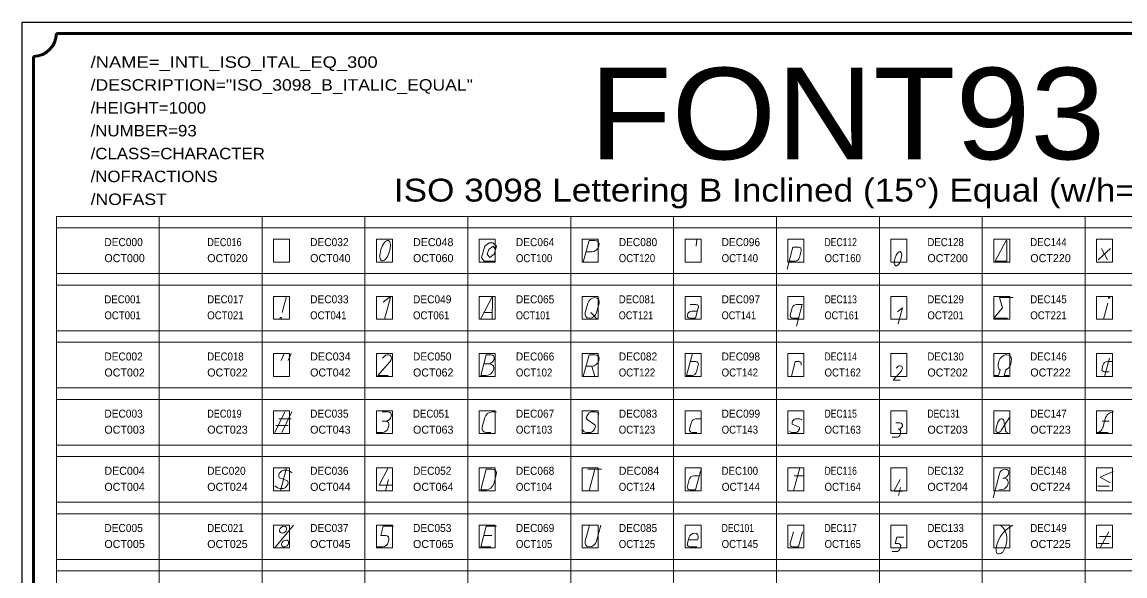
# Model space of a CAD drawing. Extents: x -200 to 7300, y -200 to 4800.
# Drawn here: x -200 to 4624, y 2378 to 4800 of the extents above; entities that cross this region are included whole.
import ezdxf
from ezdxf.enums import TextEntityAlignment as Align

# ---------------------------------------------------------------- set-up
doc = ezdxf.new("R2010")
doc.units = 0
doc.header["$LTSCALE"] = 14
for name, color, linetype, lineweight in [('1', 7, 'Continuous', 13), ('5', 7, 'Continuous', 40), ('6', 7, 'Continuous', 13), ('63', 7, 'Continuous', 13)]:
    doc.layers.add(name, color=color, linetype=linetype, lineweight=lineweight)
doc.layers.add('10', color=7, linetype='Continuous')
doc.layers.add('11', color=7, linetype='Continuous')

msp = doc.modelspace()

# ---------------------------------------------------------------- linework, layer by layer
at = {"layer": '1'}
for p, q in [((2749, 3820), (2752, 3850)), ((2292, 3795), (2267, 3795)), ((3208, 3800), (3200, 3770)), ((4507, 3760), (4561, 3810)), ((4521, 3810), (4547, 3760)), ((3181, 3755), (3156, 3755)), ((938, 3530), (957, 3600)), ((2274, 3570), (2263, 3530)), ((2324, 3570), (2313, 3530)), ((4549, 3570), (4530, 3500)), ((1821, 3530), (1857, 3530)), ((2315, 3500), (2288, 3530)), ((2722, 3565), (2747, 3565)), ((2729, 3535), (2754, 3535)), ((3168, 3550), (3160, 3520)), ((3171, 3505), (3196, 3505)), ((934, 3320), (947, 3350)), ((977, 3350), (964, 3320)), ((4556, 3330), (4535, 3250)), ((1845, 3305), (1820, 3305)), ((2292, 3295), (2267, 3295)), ((2305, 3250), (2292, 3295)), ((2747, 3315), (2722, 3315)), ((2750, 3270), (2758, 3300)), ((4072, 3315), (4070, 3305)), ((4127, 3315), (4125, 3305)), ((4528, 3300), (4524, 3285)), ((4567, 3315), (4547, 3315)), ((4535, 3270), (4555, 3270)), ((906, 3005), (950, 3095)), ((936, 3005), (980, 3095)), ((1400, 3095), (1375, 3095)), ((1875, 3095), (1855, 3095)), ((923, 3065), (977, 3065)), ((1390, 3055), (1375, 3055)), ((1824, 3070), (1813, 3030)), ((2728, 3050), (2720, 3020)), ((2767, 3065), (2747, 3065)), ((3168.8, 3041), (3199.6, 3029)), ((3640, 3047), (3622, 3047)), ((4068, 3050), (4060, 3020)), ((4119, 3070), (4083, 3015)), ((4101, 3016), (4093.7, 3055.8)), ((4525, 3055), (4555, 3055)), ((4527, 3025), (4537, 3065)), ((910, 3035), (964, 3035)), ((1376, 3005), (1351, 3005)), ((1404, 3035), (1402, 3025)), ((1831, 3005), (1851, 3005)), ((2731, 3005), (2751, 3005)), ((3633, 3019), (3632.8, 3019)), ((3643, 3005), (3641.3, 2998)), ((4551, 3005), (4501, 3005)), ((3624, 2984), (3606, 2984)), ((957, 2850), (930, 2750)), ((3202, 2850), (3175, 2750)), ((1390, 2750), (1403, 2800)), ((1874, 2820), (1863, 2780)), ((2275, 2845), (2335, 2845)), ((2305, 2845), (2280, 2750)), ((2710, 2770), (2718, 2800)), ((2737, 2815), (2762, 2815)), ((3177, 2815), (3217, 2815)), ((4047, 2720), (4075, 2825)), ((4089.6, 2805), (4094.6, 2805)), ((3633, 2730), (3642, 2765)), ((4505, 2770), (4555, 2770)), ((905, 2500), (987, 2600)), ((2282, 2600), (2263, 2530)), ((2332, 2600), (2313, 2530)), ((3174, 2570), (3160, 2520)), ((4515, 2500), (4554, 2570)), ((1404, 2535), (1402, 2525)), ((1855, 2555), (1820, 2555)), ((2710, 2520), (2717, 2545)), ((4505, 2520), (4555, 2520)), ((4513, 2550), (4563, 2550)), ((1351, 2505), (1376.6, 2505)), ((2751, 2505), (2721, 2505)), ((3606, 2484), (3624, 2484)), ((3643, 2505), (3641, 2498))]:
    msp.add_line(p, q, dxfattribs=at)
for points in [[(1871, 3755), (1821, 3755), (1810, 3770), (1824, 3820), (1843, 3835), (1859, 3835), (1875, 3820), (1865, 3785), (1846, 3770), (1835, 3785), (1841, 3805), (1860, 3820), (1871, 3805)], [(2305, 3845), (2280, 3845), (2255, 3750)], [(3147, 3720), (3172, 3815), (3197, 3815)], [(1385, 3500), (1411, 3595), (1406, 3595), (1380, 3575)], [(1805, 3500), (1855, 3595), (1858, 3595), (1856, 3500)], [(4135, 3595), (4075, 3595), (4088, 3550), (4051, 3505), (4111, 3505)], [(2758, 3550), (2746, 3505), (2721, 3505)], [(3187, 3470), (3212, 3565), (3187, 3565)], [(3632, 3480), (3651, 3550), (3629, 3533)], [(1850, 3345), (1830, 3345), (1806, 3255), (1831, 3255)], [(2305, 3345), (2280, 3345), (2255, 3250)], [(2732, 3350), (2706, 3255), (2731, 3255)], [(1401, 3255), (1356, 3255), (1409, 3314)], [(3197, 3315), (3182, 3315), (3165, 3250)], [(3641, 3234), (3610, 3234), (3646, 3275)], [(4051, 3255), (4071, 3255), (4078, 3279)], [(4116, 3255), (4096, 3255), (4103, 3279)], [(2322, 3083), (2322, 3088), (2318, 3092), (2314, 3094), (2307, 3095), (2290, 3095), (2286, 3094), (2281, 3091), (2276, 3085), (2273, 3081), (2271, 3077), (2268, 3069), (2272, 3062), (2305, 3038), (2308, 3031), (2306, 3023), (2304, 3019), (2301, 3015), (2295, 3009), (2291, 3006), (2286, 3005), (2269, 3005), (2263, 3006), (2259, 3008), (2255, 3012), (2255, 3017)], [(1417, 2775), (1362, 2775), (1402, 2850)], [(2772, 2850), (2746, 2755), (2721, 2755)], [(981, 2828), (968, 2837), (959, 2840), (944, 2840), (940, 2839), (935, 2836), (928.6, 2830.8), (925, 2827), (923, 2819), (923.2, 2813), (925.5, 2807.1), (961, 2793), (964, 2786), (962, 2778), (960, 2774), (957, 2770), (952, 2764), (947, 2761), (943, 2760), (928, 2760), (918, 2763), (906, 2772)], [(1855, 2845), (1830, 2845), (1806, 2755), (1831, 2755)], [(3651, 2748), (3613, 2748), (3641, 2800)], [(4573, 2835), (4516, 2810), (4559, 2785)], [(1425, 2595), (1380, 2595), (1370, 2555), (1390, 2555)], [(1875, 2595), (1830, 2595), (1806, 2505), (1851, 2505)], [(3171, 2505), (3196, 2505), (3214, 2570)], [(2714, 2535), (2754, 2535), (2757, 2545)], [(3657, 2547), (3626, 2547), (3619, 2519), (3633, 2519)]]:
    msp.add_lwpolyline(points, dxfattribs=at)
for points in [[(4056, 3755), (4107, 3755), (4108, 3845), (4105, 3845)], [(4551, 3592), (4557, 3592), (4559, 3598), (4553, 3598)], [(927, 3502), (933, 3502), (935, 3508), (929, 3508)]]:
    msp.add_lwpolyline(points, close=True, dxfattribs=at)
for centre, major_axis, ratio in [((1388.16, 3800), (14.6, 44.6), 0.408607), ((3631.31, 3765), (10.22, 31.22), 0.408607), ((941.76, 2579.84), (-12.94, -11.3), 0.762607), ((950.45, 2519.85), (-12.94, -11.3), 0.762607)]:
    msp.add_ellipse(centre, major_axis=major_axis, ratio=ratio, dxfattribs=at)
for centre, major_axis, ratio, start_param, end_param in [((2298.3, 3820), (21.5, 18.81), 0.765566, 3.860429, 7.0020216), ((3193, 3800), (-12.9, -11.29), 0.765566, 2.2896327, 3.860429), ((3185.15, 3770), (-12.9, -11.29), 0.765566, 0.7188363, 2.2896326), ((2299, 3570), (-21.5, -18.81), 0.765566, 2.2896326, 5.4312252), ((2288, 3530), (21.5, 18.81), 0.765566, 2.2896328, 5.4312254), ((2725.02, 3520), (-12.9, -11.29), 0.765566, 3.860429, 7.0020216), ((2743.2, 3550), (-12.9, -11.29), 0.765566, 2.2896327, 3.860429), ((3182.98, 3550), (-12.9, -11.29), 0.765566, 3.860429, 5.4312252), ((3175.02, 3520), (12.9, 11.29), 0.765566, 2.2896328, 3.860429), ((1395.12, 3324.87), (-17.2, -15.05), 0.765566, 1.7153279, 5.1862467), ((1844.9, 3325), (17.2, 15.05), 0.765566, 3.860429, 7.0020216), ((2298.3, 3320), (21.5, 18.81), 0.765566, 3.860429, 7.0020216), ((4099.5, 3315), (-21.63, -25.32), 0.743855, 2.1369211, 5.2785137), ((1837.84, 3280), (21.5, 18.81), 0.765566, 3.860429, 7.0020216), ((2743, 3300), (-12.9, -11.29), 0.765566, 2.2896327, 3.860429), ((3192.98, 3300), (-12.9, -11.29), 0.765566, 2.2896327, 3.860429), ((3636.28, 3282.61), (-12.04, -10.54), 0.765566, 1.7153279, 5.1862467), ((4100, 3305), (-25.87, -22.6), 0.762607, 5.4301257, 6.4773233), ((4095, 3305), (-25.87, -22.6), 0.762607, 1.2413355, 2.2885329), ((4539.02, 3285), (12.9, 11.29), 0.765566, 2.2896328, 3.860429), ((4543, 3300), (-12.9, -11.29), 0.765566, 3.860429, 5.4312252), ((2735, 3270), (-12.9, -11.29), 0.765566, 0.7188363, 2.2896326), ((1394.91, 3075), (17.2, 15.05), 0.765566, 3.860429, 7.0020216), ((1849, 3070), (-21.5, -18.81), 0.765566, 3.860429, 5.4312252), ((4567.27, 3065), (25.8, 22.58), 0.765566, 0.7188365, 2.2896328), ((1384.19, 3035), (-17.2, -15.05), 0.765566, 2.2896326, 3.8604289), ((2742.98, 3050), (-12.9, -11.29), 0.765566, 3.860429, 5.4312252), ((3183.23, 3050), (-12.9, -11.29), 0.765566, 4.1387286, 6.0747263), ((3190.91, 3060), (-20.04, -0.36), 0.248806, 3.0702852, 5.1041698), ((3636.26, 3032.98), (-12.06, -10.55), 0.765566, 0.7710374, 3.8615683), ((4080.72, 3049.84), (-8.85, -13.65), 0.702522, 2.4028539, 5.1395547), ((1381.51, 3025), (17.2, 15.05), 0.765566, 3.860429, 5.4312252), ((1838, 3030), (21.5, 18.81), 0.765566, 2.2896328, 3.860429), ((2735.02, 3020), (12.9, 11.29), 0.765566, 2.2896328, 3.860429), ((3177.37, 3010.06), (-20.04, -0.36), 0.248806, 6.2118779, 8.2948037), ((3185.2, 3020), (-12.9, -11.29), 0.765566, 1.0312547, 2.9331337), ((3627.31, 2998), (12.04, 10.54), 0.765566, 3.860429, 5.4312252), ((3629, 3005), (-12.04, -10.54), 0.765566, 2.2896326, 3.8604293), ((4072.64, 3019.84), (-8.94, -13.61), 0.705186, 5.1460808, 8.0584106), ((4116.54, 3020.31), (12.94, 11.3), 0.762607, 2.5799897, 3.8593292), ((4506.55, 3025), (-17.2, -15.05), 0.765566, 0.7188363, 2.2896326), ((1849, 2820), (-21.5, -18.81), 0.765566, 2.2896326, 3.8604289), ((2732.98, 2800), (-12.9, -11.29), 0.765566, 3.860429, 5.4312252), ((4094.96, 2825), (-17.2, -15.05), 0.765566, 0.7188364, 5.4312253), ((4087.9, 2780), (-21.5, -18.81), 0.765566, 0.4738577, 3.8604291), ((1838, 2780), (-21.5, -18.81), 0.765566, 0.7188363, 2.2896326), ((2725.02, 2770), (12.9, 11.29), 0.765566, 2.2896328, 3.860429), ((2736.92, 2545), (-17.2, -15.05), 0.765566, 2.2896326, 5.4312252), ((4163.9, 2515), (-86.02, -75.26), 0.765566, 4.4152401, 5.7335524), ((4003.9, 2515), (-86.02, -75.26), 0.765566, 1.9520105, 3.3056179), ((1382, 2525), (-17.2, -15.05), 0.765566, 0.7188366, 2.2896326), ((1384.22, 2535), (-17.2, -15.05), 0.765566, 2.2896326, 3.8604289), ((2288, 2530), (21.5, 18.81), 0.765566, 2.2896328, 5.4312254), ((2725.02, 2520), (12.9, 11.29), 0.765566, 2.2896328, 3.860429), ((3175.02, 2520), (12.9, 11.29), 0.765566, 2.2896328, 3.860429), ((3629, 2505), (-12.04, -10.54), 0.765566, 2.2896326, 3.8604289), ((3627, 2498), (12.04, 10.54), 0.765566, 3.860429, 5.4312252), ((4077.2, 2490), (-13.76, -12.04), 0.772879, 5.7364599, 8.0536718)]:
    msp.add_ellipse(centre, major_axis=major_axis, ratio=ratio, start_param=start_param, end_param=end_param, dxfattribs=at)
at = {"layer": '5', "lineweight": 53}
for p, q in [((-50, 4750), (7150, 4750)), ((-150, -50), (-150, 4650))]:
    msp.add_line(p, q, dxfattribs=at)
at = {"layer": '5', "lineweight": 25}
msp.add_lwpolyline([(-200, -200), (-200, 4800), (7300, 4800), (7300, -200)], close=True, dxfattribs=at)
at = {"layer": '5', "lineweight": 53}
msp.add_arc((-150, 4750), 100, 270, 0, dxfattribs=at)
at = {"layer": '6'}
for p, q in [((-50, 3950), (7150, 3950)), ((-50, 3950), (-50, -50)), ((400, 3950), (400, -50)), ((850, 3950), (850, -50)), ((1300, 3950), (1300, -50)), ((1750, 3950), (1750, -50)), ((2200, 3950), (2200, -50)), ((2650, 3950), (2650, -50)), ((3100, 3950), (3100, -50)), ((3550, 3950), (3550, -50)), ((4000, 3950), (4000, -50)), ((4450, 3950), (4450, -50)), ((-50, 3900), (7150, 3900)), ((-50, 3700), (7150, 3700)), ((-50, 3650), (7150, 3650)), ((-50, 3450), (7150, 3450)), ((-50, 3400), (7150, 3400)), ((-50, 3200), (7150, 3200)), ((-50, 3150), (7150, 3150)), ((-50, 2950), (7150, 2950)), ((-50, 2900), (7150, 2900)), ((-50, 2700), (7150, 2700)), ((-50, 2650), (7150, 2650)), ((-50, 2450), (7150, 2450)), ((-50, 2400), (7150, 2400))]:
    msp.add_line(p, q, dxfattribs=at)
at = {"layer": '63'}
for points in [[(900, 3750), (970, 3750), (970, 3850), (900, 3850)], [(1350, 3750), (1420, 3750), (1420, 3850), (1350, 3850)], [(1800, 3750), (1870, 3750), (1870, 3850), (1800, 3850)], [(2250, 3750), (2320, 3750), (2320, 3850), (2250, 3850)], [(2700, 3750), (2770, 3750), (2770, 3850), (2700, 3850)], [(3150, 3750), (3220, 3750), (3220, 3850), (3150, 3850)], [(3600, 3750), (3670, 3750), (3670, 3850), (3600, 3850)], [(4050, 3750), (4120, 3750), (4120, 3850), (4050, 3850)], [(4500, 3750), (4570, 3750), (4570, 3850), (4500, 3850)], [(900, 3500), (970, 3500), (970, 3600), (900, 3600)], [(1350, 3500), (1420, 3500), (1420, 3600), (1350, 3600)], [(1800, 3500), (1870, 3500), (1870, 3600), (1800, 3600)], [(2250, 3500), (2320, 3500), (2320, 3600), (2250, 3600)], [(2700, 3500), (2770, 3500), (2770, 3600), (2700, 3600)], [(3150, 3500), (3220, 3500), (3220, 3600), (3150, 3600)], [(3600, 3500), (3670, 3500), (3670, 3600), (3600, 3600)], [(4050, 3500), (4120, 3500), (4120, 3600), (4050, 3600)], [(4500, 3500), (4570, 3500), (4570, 3600), (4500, 3600)], [(900, 3250), (970, 3250), (970, 3350), (900, 3350)], [(1350, 3250), (1420, 3250), (1420, 3350), (1350, 3350)], [(1800, 3250), (1870, 3250), (1870, 3350), (1800, 3350)], [(2250, 3250), (2320, 3250), (2320, 3350), (2250, 3350)], [(2700, 3250), (2770, 3250), (2770, 3350), (2700, 3350)], [(3150, 3250), (3220, 3250), (3220, 3350), (3150, 3350)], [(3600, 3250), (3670, 3250), (3670, 3350), (3600, 3350)], [(4050, 3250), (4120, 3250), (4120, 3350), (4050, 3350)], [(4500, 3250), (4570, 3250), (4570, 3350), (4500, 3350)], [(900, 3000), (970, 3000), (970, 3100), (900, 3100)], [(1350, 3000), (1420, 3000), (1420, 3100), (1350, 3100)], [(1800, 3000), (1870, 3000), (1870, 3100), (1800, 3100)], [(2250, 3000), (2320, 3000), (2320, 3100), (2250, 3100)], [(2700, 3000), (2770, 3000), (2770, 3100), (2700, 3100)], [(3150, 3000), (3220, 3000), (3220, 3100), (3150, 3100)], [(3600, 3000), (3670, 3000), (3670, 3100), (3600, 3100)], [(4050, 3000), (4120, 3000), (4120, 3100), (4050, 3100)], [(4500, 3000), (4570, 3000), (4570, 3100), (4500, 3100)], [(900, 2750), (970, 2750), (970, 2850), (900, 2850)], [(1350, 2750), (1420, 2750), (1420, 2850), (1350, 2850)], [(1800, 2750), (1870, 2750), (1870, 2850), (1800, 2850)], [(2250, 2750), (2320, 2750), (2320, 2850), (2250, 2850)], [(2700, 2750), (2770, 2750), (2770, 2850), (2700, 2850)], [(3150, 2750), (3220, 2750), (3220, 2850), (3150, 2850)], [(3600, 2750), (3670, 2750), (3670, 2850), (3600, 2850)], [(4050, 2750), (4120, 2750), (4120, 2850), (4050, 2850)], [(4500, 2750), (4570, 2750), (4570, 2850), (4500, 2850)], [(900, 2500), (970, 2500), (970, 2600), (900, 2600)], [(1350, 2500), (1420, 2500), (1420, 2600), (1350, 2600)], [(1800, 2500), (1870, 2500), (1870, 2600), (1800, 2600)], [(2250, 2500), (2320, 2500), (2320, 2600), (2250, 2600)], [(2700, 2500), (2770, 2500), (2770, 2600), (2700, 2600)], [(3150, 2500), (3220, 2500), (3220, 2600), (3150, 2600)], [(3600, 2500), (3670, 2500), (3670, 2600), (3600, 2600)], [(4050, 2500), (4120, 2500), (4120, 2600), (4050, 2600)], [(4500, 2500), (4570, 2500), (4570, 2600), (4500, 2600)]]:
    msp.add_lwpolyline(points, close=True, dxfattribs=at)

# ---------------------------------------------------------------- texts
at = {"layer": '10'}
for s, width, p in [('DEC000', 0.95, (160, 3820)), ('DEC016', 0.85, (610, 3820)), ('DEC032', 0.95, (1060, 3820)), ('DEC064', 0.95, (1960, 3820)), ('DEC080', 0.95, (2410, 3820)), ('DEC096', 0.95, (2860, 3820)), ('DEC112', 0.8, (3310, 3820)), ('DEC128', 0.9, (3760, 3820)), ('DEC144', 0.9, (4210, 3820)), ('DEC001', 0.9, (160, 3570)), ('DEC017', 0.9, (610, 3570)), ('DEC033', 0.95, (1060, 3570)), ('DEC049', 0.95, (1510, 3570)), ('DEC065', 0.95, (1960, 3570)), ('DEC081', 0.9, (2410, 3570)), ('DEC097', 0.95, (2860, 3570)), ('DEC113', 0.8, (3310, 3570)), ('DEC129', 0.9, (3760, 3570)), ('DEC145', 0.9, (4210, 3570)), ('DEC002', 0.95, (160, 3320)), ('DEC018', 0.9, (610, 3320)), ('DEC050', 0.95, (1510, 3320)), ('DEC066', 0.95, (1960, 3320)), ('DEC082', 0.95, (2410, 3320)), ('DEC098', 0.95, (2860, 3320)), ('DEC114', 0.8, (3310, 3320)), ('DEC130', 0.9, (3760, 3320)), ('DEC146', 0.9, (4210, 3320)), ('DEC003', 0.95, (160, 3070)), ('DEC019', 0.85, (610, 3070)), ('DEC035', 0.95, (1060, 3070)), ('DEC051', 0.9, (1510, 3070)), ('DEC067', 0.95, (1960, 3070)), ('DEC083', 0.95, (2410, 3070)), ('DEC099', 0.95, (2860, 3070)), ('DEC115', 0.8, (3310, 3070)), ('DEC131', 0.8, (3760, 3070)), ('DEC147', 0.9, (4210, 3070)), ('DEC020', 0.95, (610, 2820)), ('DEC036', 0.95, (1060, 2820)), ('DEC052', 0.95, (1510, 2820)), ('DEC068', 0.95, (1960, 2820)), ('DEC100', 0.9, (2860, 2820)), ('DEC116', 0.8, (3310, 2820)), ('DEC132', 0.9, (3760, 2820)), ('DEC148', 0.9, (4210, 2820)), ('DEC005', 0.95, (160, 2570)), ('DEC021', 0.9, (610, 2570)), ('DEC037', 0.95, (1060, 2570)), ('DEC053', 0.95, (1510, 2570)), ('DEC069', 0.95, (1960, 2570)), ('DEC085', 0.95, (2410, 2570)), ('DEC101', 0.8, (2860, 2570)), ('DEC117', 0.8, (3310, 2570)), ('DEC133', 0.9, (3760, 2570)), ('DEC149', 0.9, (4210, 2570))]:
    msp.add_text(s, height=35, dxfattribs=dict(at, width=width)).set_placement(p)
for s, p in [('DEC048', (1510, 3820)), ('DEC034', (1060, 3320)), ('DEC004', (160, 2820)), ('DEC084', (2410, 2820))]:
    msp.add_text(s, height=35, dxfattribs=at).set_placement(p)
at = {"layer": '11'}
for s, p in [('OCT000', (160, 3750)), ('OCT020', (610, 3750)), ('OCT040', (1060, 3750)), ('OCT060', (1510, 3750)), ('OCT200', (3760, 3750)), ('OCT220', (4210, 3750)), ('OCT002', (160, 3250)), ('OCT022', (610, 3250)), ('OCT042', (1060, 3250)), ('OCT062', (1510, 3250)), ('OCT202', (3760, 3250)), ('OCT222', (4210, 3250)), ('OCT003', (160, 3000)), ('OCT023', (610, 3000)), ('OCT043', (1060, 3000)), ('OCT063', (1510, 3000)), ('OCT203', (3760, 3000)), ('OCT223', (4210, 3000)), ('OCT004', (160, 2750)), ('OCT024', (610, 2750)), ('OCT044', (1060, 2750)), ('OCT064', (1510, 2750)), ('OCT204', (3760, 2750)), ('OCT224', (4210, 2750)), ('OCT005', (160, 2500)), ('OCT025', (610, 2500)), ('OCT045', (1060, 2500)), ('OCT065', (1510, 2500)), ('OCT205', (3760, 2500)), ('OCT225', (4210, 2500))]:
    msp.add_text(s, height=35, dxfattribs=at).set_placement(p)
for s, width, p in [('OCT100', 0.9, (1960, 3750)), ('OCT120', 0.9, (2410, 3750)), ('OCT140', 0.9, (2860, 3750)), ('OCT160', 0.9, (3310, 3750)), ('OCT001', 0.9, (160, 3500)), ('OCT021', 0.9, (610, 3500)), ('OCT041', 0.9, (1060, 3500)), ('OCT061', 0.9, (1510, 3500)), ('OCT101', 0.85, (1960, 3500)), ('OCT121', 0.85, (2410, 3500)), ('OCT141', 0.85, (2860, 3500)), ('OCT161', 0.85, (3310, 3500)), ('OCT201', 0.9, (3760, 3500)), ('OCT221', 0.9, (4210, 3500)), ('OCT102', 0.9, (1960, 3250)), ('OCT122', 0.9, (2410, 3250)), ('OCT142', 0.9, (2860, 3250)), ('OCT162', 0.9, (3310, 3250)), ('OCT103', 0.9, (1960, 3000)), ('OCT123', 0.9, (2410, 3000)), ('OCT143', 0.9, (2860, 3000)), ('OCT163', 0.9, (3310, 3000)), ('OCT104', 0.9, (1960, 2750)), ('OCT124', 0.9, (2410, 2750)), ('OCT144', 0.95, (2860, 2750)), ('OCT164', 0.9, (3310, 2750)), ('OCT105', 0.9, (1960, 2500)), ('OCT125', 0.9, (2410, 2500)), ('OCT145', 0.9, (2860, 2500)), ('OCT165', 0.9, (3310, 2500))]:
    msp.add_text(s, height=35, dxfattribs=dict(at, width=width)).set_placement(p)
at = {"layer": '5'}
for s, height, width, p in [('FONT93', 400, 1.1, (3409.5, 4200)), ('ISO 3098 Lettering B Inclined (15°) Equal (w/h=7/10)', 100, 1.15, (3224.5, 4015))]:
    msp.add_text(s, height=height, dxfattribs=dict(at, width=width)).set_placement(p, align=Align.CENTER)
at = {"layer": '63'}
for s, width, p in [('/NAME=_INTL_ISO_ITAL_EQ_300', 1.2, (100, 4600)), ('/DESCRIPTION="ISO_3098_B_ITALIC_EQUAL"', 1.15, (100, 4500)), ('/HEIGHT=1000', 1.1, (100, 4400)), ('/NUMBER=93', 1.1, (100, 4300)), ('/CLASS=CHARACTER', 1.1, (100, 4200)), ('/NOFRACTIONS', 1.1, (100, 4100)), ('/NOFAST', 1.15, (100, 4000))]:
    msp.add_text(s, height=50, dxfattribs=dict(at, width=width)).set_placement(p)

doc.saveas('drawing.dxf')
